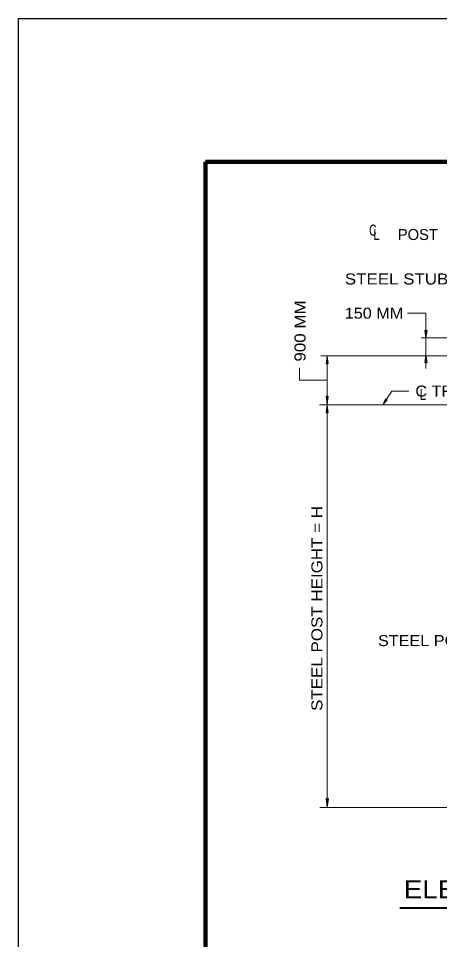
# Model space of a CAD drawing. Extents: x 312601.858 to 312602.699, y 144420.109 to 144420.704.
# Drawn here: x 312601.8578 to 312601.9725, y 144420.4528 to 144420.7035 of the extents above; entities that cross this region are included whole.
import ezdxf
from ezdxf.enums import TextEntityAlignment as Align

# ---------------------------------------------------------------- set-up
doc = ezdxf.new("R2010")
doc.units = 0
doc.header["$LTSCALE"] = 0.0012
for name, color, linetype, lineweight in [('1', 7, 'Continuous', 13), ('2', 7, 'Continuous', 25), ('39', 7, 'Continuous', 13)]:
    doc.layers.add(name, color=color, linetype=linetype, lineweight=lineweight)

msp = doc.modelspace()

# ---------------------------------------------------------------- hatches: boundary and pattern name
at = {"layer": '39'}
for points in [[(312601.9579, 144420.5997), (312601.9582, 144420.5997), (312601.9571, 144420.5984), (312601.9578, 144420.6)], [(312601.9419, 144420.491), (312601.9423, 144420.4912), (312601.9419, 144420.4888), (312601.9416, 144420.4912)]]:
    msp.add_hatch(color=256, dxfattribs=at).paths.add_polyline_path(points)

# ---------------------------------------------------------------- linework, layer by layer
at = {"layer": '1'}
for p, q in [((312601.9675, 144420.6166), (312601.9928, 144420.6166)), ((312601.9402, 144420.6117), (312601.985, 144420.6117)), ((312601.9869, 144420.5984), (312601.9398, 144420.5984)), ((312601.9898, 144420.4888), (312601.9399, 144420.4888))]:
    msp.add_line(p, q, dxfattribs=at)
for points in [[(312601.9688, 144420.6233), (312601.9688, 144420.6166), (312601.9688, 144420.6131), (312601.9688, 144420.6082)], [(312601.9419, 144420.4888), (312601.9419, 144420.5984), (312601.9419, 144420.6117)]]:
    msp.add_lwpolyline(points, dxfattribs=at)
for points in [[(312601.9691, 144420.6187), (312601.9688, 144420.6164), (312601.9685, 144420.6187), (312601.9688, 144420.6184)], [(312601.9416, 144420.6095), (312601.9419, 144420.6117), (312601.9422, 144420.6095), (312601.9419, 144420.6097)], [(312601.9685, 144420.6098), (312601.9688, 144420.612), (312601.9691, 144420.6098), (312601.9688, 144420.61)], [(312601.9422, 144420.6007), (312601.9419, 144420.5984), (312601.9416, 144420.6007), (312601.9419, 144420.6004)], [(312601.9422, 144420.6007), (312601.9419, 144420.5984), (312601.9416, 144420.6007), (312601.9419, 144420.6004)], [(312601.9416, 144420.5962), (312601.9419, 144420.5984), (312601.9422, 144420.5962), (312601.9419, 144420.5964)], [(312601.9416, 144420.5962), (312601.9419, 144420.5984), (312601.9422, 144420.5962), (312601.9419, 144420.5964)], [(312601.9416, 144420.5962), (312601.9419, 144420.5984), (312601.9422, 144420.5962), (312601.9419, 144420.5964)]]:
    msp.add_lwpolyline(points, close=True, dxfattribs=at)
at = {"layer": '2', "lineweight": 13}
for p, q in [((312601.9638, 144420.6233), (312601.9688, 144420.6233)), ((312601.9344, 144420.6084), (312601.9344, 144420.6051)), ((312601.9419, 144420.6051), (312601.9344, 144420.6051))]:
    msp.add_line(p, q, dxfattribs=at)
at = {"layer": '2', "lineweight": 40}
msp.add_line((312601.9617, 144420.4615), (312602.1529, 144420.4615), dxfattribs=at)
at = {"layer": '2', "lineweight": 13}
msp.add_lwpolyline([(312601.9641, 144420.6021), (312601.9595, 144420.6021), (312601.9571, 144420.5984)], dxfattribs=at)
at = {"layer": '39', "lineweight": 25}
for p, q in [((312601.8578, 144420.7035), (312602.6988, 144420.7035)), ((312601.8578, 144420.1095), (312601.8578, 144420.7035))]:
    msp.add_line(p, q, dxfattribs=at)
at = {"layer": '39', "lineweight": 158}
for p, q in [((312601.9088, 144420.6645), (312602.6838, 144420.6645)), ((312601.9088, 144420.1247), (312601.9088, 144420.6645))]:
    msp.add_line(p, q, dxfattribs=at)
at = {"layer": '39'}
for points in [[(312601.9579, 144420.5997), (312601.9582, 144420.5997), (312601.9571, 144420.5984), (312601.9578, 144420.6)], [(312601.9419, 144420.491), (312601.9423, 144420.4912), (312601.9419, 144420.4888), (312601.9416, 144420.4912)]]:
    msp.add_lwpolyline(points, close=True, dxfattribs=at)

# ---------------------------------------------------------------- texts
at = {"layer": '2'}
for s, height, width, p in [('C', 0.003, 0.7, (312601.95435, 144420.6444)), ('L', 0.003, 0.75, (312601.95535, 144420.6432)), ('STEEL STUBS', 0.003, 1.15, (312601.96235, 144420.6311)), ('150 MM', 0.003, 1.1, (312601.95465, 144420.6218)), ('C TRUSS', 0.003, 1.1, (312601.9756, 144420.6006)), ('L', 0.003, 0.75, (312601.96795, 144420.5997)), ('STEEL POST', 0.003, 1.1, (312601.96935, 144420.5327)), ('ELEVATION - TYPICAL CANTILEVER SIGN SUPPORT', 0.0049, 1.15, (312602.0572, 144420.4641))]:
    msp.add_text(s, height=height, dxfattribs=dict(at, width=width)).set_placement(p, align=Align.CENTER)
msp.add_text('POST', height=0.003, dxfattribs=at).set_placement((312601.9666, 144420.6432), align=Align.CENTER)
at = {"layer": '2', "width": 1.15}
for s, p in [('900 MM', (312601.936, 144420.61845)), ('STEEL POST HEIGHT = H', (312601.9406, 144420.54295))]:
    msp.add_text(s, height=0.003, rotation=90, dxfattribs=at).set_placement(p, align=Align.CENTER)

doc.saveas('drawing.dxf')
